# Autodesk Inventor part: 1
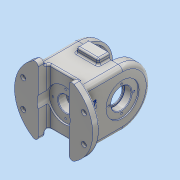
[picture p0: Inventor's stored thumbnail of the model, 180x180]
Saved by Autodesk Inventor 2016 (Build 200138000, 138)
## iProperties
Created: 2024-08
Part Number: 1
Material: 알루미늄 6061
Document SubType Name: Modeling
Designer: pc-2
Density: 2.7 g/cm^3
Appearance: 알루미늄 - 평지
Mass: 1199.05 g
Surface Area: 1051.82 cm^2
Volume: 444.094 cm^3
Author: pc-2
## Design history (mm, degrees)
sketch "스케치1"
  geometry: C1 r 71 at (0, 0); 1 further point
  constraints: 1 centre point, 1 coincident
  dimensions: "d0" = 142 diameter of C1
extrude "돌출1" new body sketch "스케치1" distance "d1" = 13; taper "d2" = 0 deg
sketch "스케치2"
  geometry: L1 (81, 51)-(13, 51); L2 (13, 51)-(13, -51); L3 (13, -71)-(13, 71) reference; L4 (81, -51)-(13, -51); L5 (81, 0)-(13, 0); L6 (0, 71)-(0, -71) reference; A1 r 51 centre (81, 0) between (81, 51) and (81, -51); 1 further point
  constraints: 8 end point, 2 horizontal, 2 point on circle, 2 point on line, 2 tangent, 1 centre point, 1 midpoint, 1 perpendicular
  dimensions: "d3" = 102 diameter of A1; "d4" = 81 distance from line of L6 L5.start
extrude "돌출2" join sketch "스케치2" stored distance "d5" = 88; taper "d6" = 0 deg
sketch "스케치3"
  geometry: L1 (-28, 0)-(28, 0); L2 (28, 0)-(28, 19); L3 (28, 19)-(-28, 19); L4 (-28, 19)-(-28, 0); L5 (0, 19)-(0, 0)
  constraints: 10 end point, 2 parallel, 1 horizontal, 1 midpoint, 1 perpendicular, 1 vertical
  dimensions: "d7" = 56 distance of L2.end L3.end; "d8" = 19 distance of L1.end L2.end
extrude "돌출3" cut sketch "스케치3" stored distance "d9" = 256; taper "d10" = 0 deg
sketch "스케치4"
  geometry: L1 (0, 51)-(88, 51) reference; L2 (0, 0)-(88, 0) reference; L3 (19, 51)-(69, 51); L4 (69, 51)-(69, 0); L5 (69, 0)-(19, 0); L6 (19, 0)-(19, 51); L7 (44, 0)-(44, -81)
  constraints: 10 end point, 2 parallel, 2 point on line, 1 horizontal, 1 midpoint, 1 perpendicular, 1 vertical
  dimensions: "d11" = 50 distance between parallel lines of L6 L4
extrude "돌출4" cut sketch "스케치4" distance "d12" = 574.25; taper "d13" = 0 deg
sketch "스케치5"
  geometry: L1 (81, 51)-(81, -51) reference; L2 (81, 46)-(40, 46); L3 (40, 46)-(40, -46); L4 (40, -46)-(81, -46); L5 (81, -46)-(81, 46); L6 (0, -65.246)-(0, 65.246) reference; A1 r 51 centre (81, 0) between (81, -51) and (81, 51) reference; A2 r 46 centre (81, 0) between (40, -20.857) and (40, 20.857); 1 further point
  constraints: 8 end point, 3 point on circle, 3 point on line, 2 parallel, 1 centre point, 1 coincident, 1 horizontal, 1 perpendicular, 1 tangent
  dimensions: "d14" = 5 radial gap between concentric circles of A1 A2; "d15" = 40 distance between parallel lines of L6 L3
extrude "돌출5" cut sketch "스케치5" stored distance "d16" = 78; taper "d17" = 0 deg
sketch "스케치6"
  geometry: L1 (0, 0)-(-30, 0); L2 (-30, 0)-(-30, 22); L3 (-30, 22)-(0, 22); L4 (0, 22)-(0, 0); L5 (0, 22)-(-14, 22); L6 (-14, 22)-(-14, 37); L7 (-14, 37)-(0, 37); L8 (0, 37)-(0, 22); L9 (-39, 40)-(39, 40) reference; L10 (0, 37)-(-11, 37); L11 (-11, 37)-(-11, 40); L12 (-11, 40)-(0, 40); L13 (0, 40)-(0, 37)
  constraints: 24 end point, 6 parallel, 3 horizontal, 3 perpendicular, 1 point on line
  dimensions: "d18" = 30 distance of L2.end L3.end; "d19" = 22 distance of L1.end L2.end; "d20" = 15 distance of L5.end L6.end; "d21" = 14 distance of L6.end L7.end; "d22" = 11 distance between parallel lines of L13 L11
revolve "회전1" sketch "스케치6" stored, may be unused: angle "d23" = 90 deg
sketch "스케치7"
  geometry: A1 r 23 centre (0, 0) between (0, 23) and (-23, 0); 3 further points
  constraints: 4 point on circle, 1 centre point, 1 coincident
  dimensions: "d24" = 46 diameter of A1
hole "구멍1" sketch "스케치7" at (0, 23), (-23, 0), (0, -23), (23, 0) diameter "d25" = 3.242; stored, may be unused: countersink angle "d29" = 90 deg, drill point angle "d31" = 118 deg; dims "d26" = 8, "d27" = 4, "d28" = 2, "d30" = 10
sketch "스케치8"
  geometry: L1 (-39, 127)-(-39, 81) reference; L2 (-39, 114.5)-(-27, 102.5); L3 (-27, 102.5)-(-27, 81); L4 (-39, 81)-(-25, 81) reference; L5 (-27, 81)-(-39, 81); 1 further point
  constraints: 6 end point, 1 collinear, 1 parallel, 1 point on line
  dimensions: "d32" = 33.5 distance from line of L4 L2.start; "d33" = 12 horizontal distance of L2.start L2.end; "d34" = 45 deg angle of L1 L2
revolve "회전2" sketch "스케치8" stored, may be unused: angle "d35" = 90 deg
sketch "스케치9"
  geometry: C1 r 30 at (0, 81); A1 r 51 centre (0, 81) between (51, 81) and (-51, 81) reference; 1 further point
  constraints: 1 centre point, 1 coincident
  dimensions: "d36" = 60 diameter of C1
extrude "돌출6" cut sketch "스케치9" distance "d37" = 2; taper "d38" = 0 deg
sketch "스케치10"
  geometry: C1 r 30 at (0, 0) reference; C2 r 18.5 at (0, 0); 1 further point
  constraints: 1 centre point, 1 coincident
  dimensions: "d39" = 37 diameter of C2
extrude "돌출7" cut sketch "스케치10" distance "d40" = 13; taper "d41" = 0 deg
sketch "스케치11"
  geometry: C1 r 18.5 at (0, 0) reference; C2 r 16 at (0, 0); 1 further point
  constraints: 1 centre point, 1 coincident
  dimensions: "d42" = 32 diameter of C2
extrude "돌출8" cut sketch "스케치11" distance "d43" = 13.25; taper "d44" = 0 deg
sketch "스케치12"
  geometry: C1 r 16 at (0, 0) reference; A1 r 23 centre (0, 0) between (0, 23) and (-23, 0); 3 further points
  constraints: 4 point on circle, 1 centre point, 1 coincident
  dimensions: "d45" = 46 diameter of A1
hole "구멍2" sketch "스케치12" at (0, 23), (-23, 0), (0, -23), (23, 0) diameter "d46" = 3.242; stored, may be unused: countersink angle "d50" = 90 deg, drill point angle "d52" = 118 deg; dims "d47" = 8, "d48" = 4, "d49" = 2, "d51" = 10
sketch "스케치13"
  geometry: L1 (0, 0)-(50, 0) reference; L2 (5, 0)-(45, 0); L3 (45, 0)-(45, 10); L4 (45, 10)-(5, 10); L5 (5, 10)-(5, 0); L6 (50, -102)-(0, -102) reference; L7 (5, -102)-(45, -102); L8 (45, -102)-(45, -112); L9 (45, -112)-(5, -112); L10 (5, -112)-(5, -102); L11 (5, -102)-(45, -102); L12 (45, -102)-(45, 0); L13 (45, 0)-(5, 0); L14 (5, 0)-(5, -102); L15 (25, -51)-(25, 0)
  constraints: 26 end point, 6 parallel, 3 horizontal, 3 perpendicular, 2 point on line, 1 midpoint, 1 vertical
  dimensions: "d53" = 40 distance of L8.end L9.end; "d54" = 61 distance from line of L15.start L4; "d55" = 61 distance from line of L9 L15.start
extrude "돌출9" join sketch "스케치13" distance "d56" = 20; taper "d57" = 0 deg
sketch "스케치14"
  geometry: L1 (12, 8)-(38, 8); L2 (38, 8)-(38, -100); L3 (38, -100)-(12, -100); L4 (12, -100)-(12, 8); L5 (12, 8)-(38, -100); L6 (38, 8)-(12, -100); 5 further points
  constraints: 12 end point, 4 coincident, 2 midpoint, 2 parallel, 1 horizontal, 1 perpendicular
  dimensions: "d58" = 26 distance of L2.end L3.end; "d59" = 108 distance of L1.end L2.end
hole "구멍3" sketch "스케치14" at (12, 8), (12, -100), (38, -100), (38, 8) diameter "d60" = 3.242; stored, may be unused: countersink angle "d64" = 90 deg, drill point angle "d66" = 118 deg; dims "d61" = 8, "d62" = 4, "d63" = 2, "d65" = 10
fillet "모깎기1" dims "d67" = 0.3
fillet "모깎기2" dims "d68" = 8
fillet "모깎기3" dims "d69" = 6
sketch "스케치15"
  geometry: L1 (-55, 25)-(55, 25); L2 (55, 25)-(55, -25); L3 (55, -25)-(-55, -25); L4 (-55, -25)-(-55, 25); L5 (-55, 25)-(55, -25); L6 (55, 25)-(-55, -25); 5 further points
  constraints: 12 end point, 4 coincident, 2 midpoint, 2 parallel, 1 horizontal, 1 perpendicular
  dimensions: "d70" = 50 distance of L1.end L2.end; "d71" = 110 distance of L1.start L1.end
hole "구멍4" sketch "스케치15" at (-55, 25), (-55, -25), (55, -25), (55, 25) diameter "d72" = 9; stored, may be unused: countersink angle "d76" = 90 deg, drill point angle "d78" = 118 deg; dims "d73" = 8, "d74" = 15, "d75" = 8.8, "d77" = 10
sketch "스케치16"
  geometry: L1 (-26.595, 33.618)-(26.595, 33.618); L2 (26.595, 33.618)-(26.595, 26.382); L3 (26.595, 26.382)-(-26.595, 26.382); L4 (-26.595, 26.382)-(-26.595, 33.618); L5 (0, 26.382)-(0, 0); L6 (26.595, 30)-(-26.595, 30); L7 (-60.512, 0)-(60.512, 0) reference
  constraints: 4 end point, 3 midpoint, 1 horizontal, 1 vertical, 2 other
  dimensions: "d79" = 30 distance between parallel lines of L7 L6
extrude "돌출10" cut sketch "스케치16" distance "d80" = 0.5; taper "d81" = 0 deg
chamfer "모따기1" distance "d82" = 1; stored, may be unused: second distance "d83" = 2, angle "d84" = 45 deg
fillet "모깎기4" dims "d85" = 3
fillet "모깎기5" dims "d86" = 3
fillet "모깎기6" dims "d87" = 3
fillet "모깎기7" dims "d88" = 3
fillet "모깎기8" dims "d89" = 3
fillet "모깎기9" dims "d90" = 3
fillet "모깎기10" dims "d91" = 3
fillet "모깎기11" dims "d92" = 3
node "솔리드1"
mirror "대칭1"
